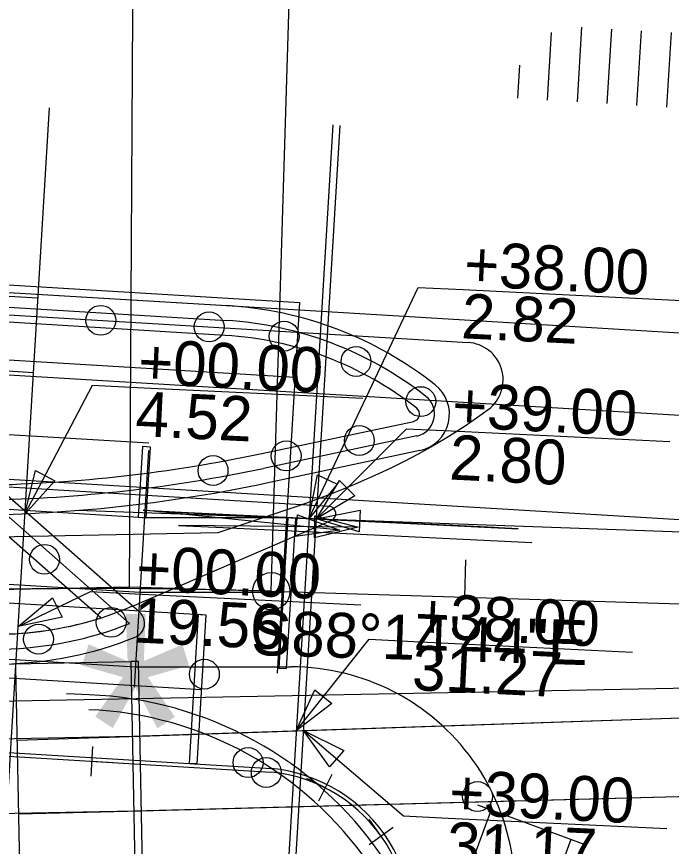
# Model space of a CAD drawing. Extents: x 659657 to 668193, y 633084 to 648639.
# Drawn here: x 662679.8 to 662767.5, y 642371.9 to 642483 of the extents above; entities that cross this region are included whole.
import ezdxf

# ---------------------------------------------------------------- set-up
doc = ezdxf.new("R2010")
doc.units = 0
for name, color, linetype in [('R_Draft', 7, 'Continuous'), ('R_MOT_Stage 1C', 7, 'Continuous'), ('R_MOT_Stage 1C_Striping', 7, 'Continuous'), ('R_MOT_Stage 2', 7, 'Continuous'), ('R_MOT_Stage 2_Striping', 7, 'Continuous'), ('R_MOT_Stage 3', 7, 'Continuous'), ('R_MOT_Stage 3_Striping', 7, 'Continuous'), ('R_MOT_Stage 4', 7, 'Continuous'), ('R_MOT_STAGE 4_ALG', 7, 'Continuous'), ('R_MOT_Stage 4_Striping', 7, 'Continuous'), ('R_MOT_Stage 5', 7, 'Continuous'), ('R_MOT_Stage 5_Striping', 7, 'Continuous'), ('R_MOT_Stage 5_Striping_PPM', 7, 'Continuous'), ('STRIPE-WHITE 12in', 7, 'Continuous'), ('T_SIGNAL CONTROL CABINET', 7, 'Continuous'), ('TEXT_TEMP_SIGNAL_POLES_STAGE 2', 7, 'Continuous')]:
    doc.layers.add(name, color=color, linetype=linetype)

msp = doc.modelspace()

# ---------------------------------------------------------------- linework, layer by layer
for p, q in [((662739.64, 642446.41), (662768.94, 642444.98)), ((662696, 642433.33), (662726.24, 642431.86)), ((662738.05, 642427.5), (662767.34, 642426.07)), ((662698.98, 642416.73), (662741.01, 642414.69)), ((662702.8, 642416.59), (662743.84, 642414.59)), ((662707.53, 642414.55), (662748.85, 642412.55)), ((662713.96, 642406.03), (662816.41, 642402.89)), ((662695.72, 642405.68), (662725.97, 642404.22)), ((662733.04, 642399.32), (662762.34, 642397.89)), ((662737.66, 642375.67), (662766.95, 642374.25))]:
    msp.add_line(p, q)
for points in [[(662719, 642415.74), (662733.65, 642446.7), (662739.64, 642446.41)], [(662680.97, 642416.34), (662690.01, 642433.62), (662696, 642433.33)], [(662720, 642415.71), (662732.05, 642427.79), (662738.05, 642427.5)], [(662723.14, 642414.22), (662696.8, 642416.88), (662702.8, 642416.59)], [(662720, 642415.71), (662747.01, 642414.4), (662741.01, 642414.69)], [(662725.58, 642414.6), (662701.54, 642414.85), (662707.53, 642414.55)], [(662680.06, 642401.32), (662689.73, 642405.98), (662695.72, 642405.68)], [(662717.28, 642387.35), (662727.05, 642399.61), (662733.04, 642399.32)], [(662718.29, 642387.39), (662731.66, 642375.97), (662737.66, 642375.67)]]:
    msp.add_lwpolyline(points)
for points in [[(662680.97, 642416.34), (662682.38, 642422.18), (662684.95, 642420.83)], [(662719, 642415.74), (662720.17, 642421.63), (662722.8, 642420.38)], [(662720, 642415.71), (662723.08, 642420.86), (662725.14, 642418.8)], [(662723.14, 642414.22), (662717.2, 642413.36), (662717.49, 642416.25)], [(662725.58, 642414.6), (662719.74, 642413.2), (662719.77, 642416.11)], [(662720, 642415.71), (662725.88, 642416.88), (662725.74, 642413.97)], [(662680.06, 642401.32), (662684.67, 642405.16), (662685.94, 642402.54)], [(662717.28, 642387.35), (662719.77, 642392.81), (662722.05, 642391)], [(662718.29, 642387.39), (662723.66, 642384.71), (662721.77, 642382.5)]]:
    msp.add_lwpolyline(points, close=True)
msp.add_arc((662690.63, 641644.39), 762, 88.24549, 91.10143)
at = {"layer": 'R_MOT_Stage 1C'}
for centre in [(662710.85, 642383.09), (662713.29, 642381.76)]:
    msp.add_circle(centre, 2, dxfattribs=at)
msp.add_arc((662687.6, 642342.21), 48, 341.5452, 87.7297, dxfattribs=at)
at = {"layer": 'R_MOT_Stage 1C_Striping'}
msp.add_line((662689.58, 642392.17), (662686.54, 642392.29), dxfattribs=at)
msp.add_arc((662687.6, 642342.21), 50, 341.5452, 87.7297, dxfattribs=at)
at = {"layer": 'R_MOT_Stage 2'}
for centre in [(662705, 642394.92), (662741.58, 642378.54)]:
    msp.add_circle(centre, 2, dxfattribs=at)
at = {"layer": 'R_MOT_Stage 2_Striping'}
for p, q in [((662564.68, 642453.94), (662717.74, 642444.7)), ((662586.38, 642442.61), (662717.14, 642434.71)), ((662585.77, 642432.63), (662697.57, 642425.88)), ((662585.17, 642422.65), (662696.97, 642415.9)), ((662696.97, 642415.9), (662716, 642415.89)), ((662584.57, 642412.66), (662696.36, 642405.91)), ((662696.36, 642405.91), (662715.4, 642405.91)), ((662695.76, 642395.93), (662716.63, 642395.91))]:
    msp.add_line(p, q, dxfattribs=at)
for points in [[(662697.2, 642415.88), (662697.78, 642425.34), (662696.72, 642425.4), (662696.15, 642415.95)], [(662716.01, 642395.68), (662717.23, 642415.8), (662716.18, 642415.86), (662714.96, 642395.74)]]:
    msp.add_lwpolyline(points, close=True, dxfattribs=at)
msp.add_lwpolyline([(662544.65, 642404.55), (662583.97, 642402.68), (662695.76, 642395.93)], dxfattribs=at)
msp.add_arc((662716.6, 642365.91), 30, 341.5452, 89.9265, dxfattribs=at)
at = {"layer": 'R_MOT_Stage 3'}
for p, q in [((662694.99, 642401.73), (662676.86, 642417.69)), ((662691.12, 642402.46), (662675.54, 642416.18))]:
    msp.add_line(p, q, dxfattribs=at)
for centre in [(662683.59, 642410.3), (662692.51, 642401.87), (662682.79, 642399.62)]:
    msp.add_circle(centre, 2, dxfattribs=at)
for radius, end in [(46, 287.7285), (48, 291.8551)]:
    msp.add_arc((662677.12, 642446.28), radius, 271.1014, end, dxfattribs=at)
at = {"layer": 'R_MOT_Stage 3_Striping'}
for p, q in [((662582.93, 642451.83), (662717.68, 642443.7)), ((662717.68, 642443.7), (662827.48, 642437.07)), ((662582.26, 642440.85), (662852.85, 642424.52)), ((662696.31, 642403.23), (662678.18, 642419.19)), ((662471.94, 642392.32), (662695.17, 642396.61)), ((662696.17, 642396.63), (662695.17, 642396.61)), ((662695.17, 642396.61), (662695.74, 642366.62)), ((662696.74, 642366.64), (662696.17, 642396.63)), ((662695.36, 642386.62), (662834.74, 642391.3)), ((662695.36, 642386.62), (662834.74, 642391.3)), ((662597.59, 642384.74), (662695.36, 642386.62)), ((662695.55, 642376.62), (662834.95, 642380.3)), ((662695.55, 642376.62), (662834.95, 642380.3)), ((662597.39, 642374.73), (662695.55, 642376.62))]:
    msp.add_line(p, q, dxfattribs=at)
for centre, radius, start, end in [((662694.99, 642401.73), 2, 291.8551, 48.6396), ((662677.12, 642446.28), 50, 271.1014, 291.8551)]:
    msp.add_arc(centre, radius, start, end, dxfattribs=at)
at = {"layer": 'R_MOT_Stage 4'}
for p, q in [((662641.18, 642446.31), (662707.9, 642442.29)), ((662707.78, 642440.29), (662641.06, 642444.32)), ((662712.49, 642424.44), (662733.03, 642428.77)), ((662733.44, 642426.82), (662712.9, 642422.48))]:
    msp.add_line(p, q, dxfattribs=at)
for centre in [(662691.12, 642442.3), (662705.63, 642441.42), (662715.68, 642440.18), (662725.31, 642436.8), (662733.98, 642431.42), (662725.75, 642426.21), (662715.96, 642424.15), (662706.16, 642422.19)]:
    msp.add_circle(centre, 2, dxfattribs=at)
for centre, radius, start, end in [((662705.01, 642394.37), 48, 51.8316, 86.5452), ((662705.01, 642394.37), 46, 51.8316, 86.5452), ((662732.82, 642429.75), 3, 281.9222, 51.8316), ((662732.82, 642429.75), 1, 281.9222, 51.8316), ((662672, 642616.21), 196, 271.1014, 281.9222), ((662672, 642616.21), 198, 271.1014, 281.9222)]:
    msp.add_arc(centre, radius, start, end, dxfattribs=at)
at = {"layer": 'R_MOT_STAGE 4_ALG'}
for p, q in [((662675.98, 642406.25), (662694.97, 642406.61)), ((662694.97, 642406.61), (662713.96, 642406.03)), ((662713.96, 642406.03), (662816.41, 642402.89))]:
    msp.add_line(p, q, dxfattribs=at)
for points in [[(662694.97, 642406.61), (662696.11, 642606.61)], [(662713.96, 642406.03), (662720.08, 642605.94)], [(662739.98, 642410.24), (662739.82, 642405.24)]]:
    msp.add_lwpolyline(points, dxfattribs=at)
msp.add_circle((662713.96, 642406.03), 2.5, dxfattribs=at)
msp.add_arc((662690.63, 641644.39), 762, 88.24549, 91.10143, dxfattribs=at)
at = {"layer": 'R_MOT_Stage 4_Striping'}
for p, q in [((662641.3, 642448.31), (662708.02, 642444.28)), ((662733.85, 642424.86), (662713.32, 642420.52)), ((662803.96, 642412.71), (662688.02, 642416.85)), ((662713.96, 642406.03), (662816.41, 642402.89)), ((662471.94, 642392.32), (662695.17, 642396.61)), ((662680.32, 642366.33), (662679.75, 642395.82)), ((662696.36, 642386.65), (662834.74, 642391.3)), ((662679.94, 642386.1), (662696.36, 642386.65)), ((662696.55, 642376.64), (662834.95, 642380.3)), ((662680.13, 642376.21), (662696.55, 642376.64))]:
    msp.add_line(p, q, dxfattribs=at)
for centre, radius, start, end in [((662705.01, 642394.37), 50, 51.8316, 86.5452), ((662732.82, 642429.75), 5, 281.9222, 51.8316), ((662672, 642616.21), 200, 271.1014, 281.9222), ((662690.63, 641644.39), 762, 88.24549, 91.10143)]:
    msp.add_arc(centre, radius, start, end, dxfattribs=at)
at = {"layer": 'R_MOT_Stage 5'}
for p, q in [((662689.84, 642381.28), (662690.08, 642385.25)), ((662690.02, 642383.26), (662692.73, 642383.09)), ((662721.13, 642379.74), (662718.71, 642380.97)), ((662722.07, 642381.48), (662720.28, 642377.93)), ((662728.65, 642373.29), (662727.08, 642375.51)), ((662730.3, 642374.39), (662727.05, 642372.09))]:
    msp.add_line(p, q, dxfattribs=at)
at = {"layer": 'R_MOT_Stage 5_Striping'}
for p, q in [((661919.1, 642491.41), (662682.71, 642445.31)), ((661918.5, 642481.43), (662682.11, 642435.33)), ((662520.53, 642414.02), (662705.2, 642402.88)), ((662410.13, 642410.67), (662704.6, 642392.89)), ((662409.53, 642400.69), (662713.96, 642382.31))]:
    msp.add_line(p, q, dxfattribs=at)
msp.add_lwpolyline([(662705.2, 642402.88), (662703.99, 642382.91), (662702.99, 642382.97), (662704.2, 642402.94)], close=True, dxfattribs=at)
msp.add_arc((662711.93, 642361.4), 21.01, 339.4107, 84.4542, dxfattribs=at)
at = {"layer": 'R_MOT_Stage 5_Striping_PPM'}
for p, q in [((662754.96, 642471.56), (662755.56, 642481.54)), ((662750.96, 642471.8), (662751.51, 642480.83)), ((662758.95, 642471.32), (662759.55, 642481.3)), ((662762.94, 642471.08), (662763.55, 642481.06)), ((662766.93, 642470.83), (662767.54, 642480.82)), ((662746.97, 642472.04), (662747.24, 642476.45))]:
    msp.add_line(p, q, dxfattribs=at)
at = {"layer": 'STRIPE-WHITE 12in'}
for p, q in [((662754.96, 642471.56), (662755.56, 642481.54)), ((662750.96, 642471.8), (662751.51, 642480.83)), ((662758.95, 642471.32), (662759.55, 642481.3)), ((662762.94, 642471.08), (662763.55, 642481.06)), ((662766.93, 642470.83), (662767.54, 642480.82)), ((662746.97, 642472.04), (662747.24, 642476.45))]:
    msp.add_line(p, q, dxfattribs=at)
at = {"layer": 'T_SIGNAL CONTROL CABINET'}
for p, q in [((662678.22, 642370.94), (662684.25, 642470.76)), ((662722.18, 642468.47), (662716.16, 642368.65)), ((662717.15, 642368.59), (662723.18, 642468.41)), ((662641.12, 642445.32), (662740.31, 642439.33)), ((662852, 642410.54), (662532, 642429.86)), ((662531.97, 642428.86), (662721.67, 642417.41)), ((662695.27, 642404.01), (662722, 642415.49)), ((662706.82, 642413.84), (662580.43, 642411.41)), ((662409.51, 642400.19), (662713.92, 642381.81)), ((663079.28, 642399), (662579.98, 642389.4))]:
    msp.add_line(p, q, dxfattribs=at)
for points in [[(662717.74, 642444.7), (662714.74, 642395.05)], [(662743.04, 642430.36), (662742.2, 642429.72), (662739.93, 642428.14), (662737.73, 642426.73), (662735.63, 642425.48), (662733.62, 642424.37), (662731.75, 642423.39), (662729.99, 642422.52), (662728.33, 642421.74), (662726.73, 642421.02), (662725.18, 642420.35), (662723.6, 642419.7), (662722.03, 642419.08), (662720.37, 642418.45), (662718.69, 642417.84), (662716.97, 642417.24), (662706.82, 642413.84)], [(662697.51, 642424.88), (662695.6, 642393.17)]]:
    msp.add_lwpolyline(points, dxfattribs=at)
for centre, radius, start, end in [((662740.01, 642434.34), 5, 307.3244, 86.5452), ((662721.61, 642416.41), 1, 293.2467, 86.5452), ((662677.12, 642446.28), 46, 270.8991, 293.2467), ((662711.93, 642361.4), 20.51, 339.4107, 84.4289)]:
    msp.add_arc(centre, radius, start, end, dxfattribs=at)
at = {"layer": 'TEXT_TEMP_SIGNAL_POLES_STAGE 2'}
for p, q in [((662741.58, 642377.45), (662756.08, 642372.07)), ((662743.41, 642376.77), (662740.03, 642367.62)), ((662754.1, 642372.81), (662750.71, 642363.66))]:
    msp.add_line(p, q, dxfattribs=at)

# ---------------------------------------------------------------- texts
for s, p in [('+38.00', (662739.67, 642446.9)), ('2.82', (662739.33, 642439.91)), ('+00.00', (662696.02, 642433.83)), ('+39.00', (662738.07, 642428)), ('4.52', (662695.68, 642426.83)), ('2.80', (662737.73, 642421)), ('+00.00', (662695.75, 642406.18)), ('19.56', (662695.41, 642399.19)), ('+38.00', (662733.07, 642399.82)), ('31.27', (662732.73, 642392.82)), ('+39.00', (662737.68, 642376.17)), ('31.17', (662737.34, 642369.18))]:
    msp.add_text(s, height=6, rotation=357.2199).set_placement(p)
at = {"layer": 'R_Draft'}
msp.add_text('*', height=30, dxfattribs=at).set_placement((662687.96, 642372.98))
at = {"layer": 'R_MOT_STAGE 4_ALG'}
msp.add_text('S88%%d14\'44"E', height=6, rotation=358.2455, dxfattribs=at).set_placement((662711.23, 642397.51))

doc.saveas('drawing.dxf')
